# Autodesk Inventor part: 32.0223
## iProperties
Created: 2011-07
Part Number: 32.0223
Document SubType Name: Modeling
Designer: Administrator
Density: 1.06 g/cm^3
Material: ABS Plastic
Mass: 5.88353 g
Surface Area: 50.3948 cm^2
Volume: 5.5505 cm^3
Description: CAP FOR C-PROFILE RAIL
Stock Number: 32.0223 CAP FOR C-PROFILE RAIL
Author: Administrator
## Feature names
1. Base1
2. Shell1
